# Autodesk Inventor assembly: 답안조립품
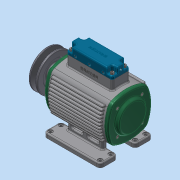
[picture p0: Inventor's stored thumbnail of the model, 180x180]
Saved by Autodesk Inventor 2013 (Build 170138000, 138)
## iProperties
Created: 2015-11
Part Number: 답안조립품
Document SubType Name: Assembly
Designer: dgall
Mass: 2616.34 g
Surface Area: 3184.98 cm^2
Volume: 1076.1 cm^3
Density: 2.43131 g/cm^3
Author: dgall
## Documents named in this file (18)
- C:\Users\dgall\Desktop\351109V1018\답안조립품.iam
- C:\Users\dgall\Desktop\351109V1018\본체.ipt
- C:\Users\dgall\Desktop\351109V1018\뒷커버.ipt
- C:\Users\dgall\Desktop\351109V1018\앞커버.ipt
- C:\Users\dgall\Desktop\351109V1018\베어링 6203.ipt
- C:\Users\dgall\Desktop\351109V1018\오일실 17 30 8.ipt
- C:\Users\dgall\Desktop\351109V1018\볼트 M4 x 12.ipt
- C:\Users\dgall\Desktop\351109V1018\축.ipt
- C:\Users\dgall\Desktop\351109V1018\부시.ipt
- C:\Users\dgall\Desktop\351109V1018\헤더커버.ipt
- C:\Users\dgall\Desktop\351109V1018\볼트 M4 x 16.ipt
- C:\Users\dgall\Desktop\351109V1018\V-벨트풀리.ipt
- C:\Users\dgall\Desktop\351109V1018\키 - 5 x 5 x 18.ipt
- C:\Users\dgall\Desktop\351109V1018\멈춤나사 M4x5.ipt
- C:\Users\dgall\Desktop\351109V1018\슬라이드.ipt
- C:\Users\dgall\Desktop\351109V1018\스프링1.ipt
- C:\Users\dgall\Desktop\351109V1018\스프링2.ipt
- C:\Users\dgall\Desktop\351109V1018\스프링3.ipt
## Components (4 placed, 3 different names)
1. 7-베어링 6203:1
2. 7-베어링 6203:2
3. 헤더커버:1
4. V-벨트풀리:1
